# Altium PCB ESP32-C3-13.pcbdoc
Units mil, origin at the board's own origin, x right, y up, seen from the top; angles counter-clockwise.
Board outline 500 x 500 mil, 2 copper layers (Top Layer, Bottom Layer); 1 components, 0 nets, 18 pads, 0 vias.
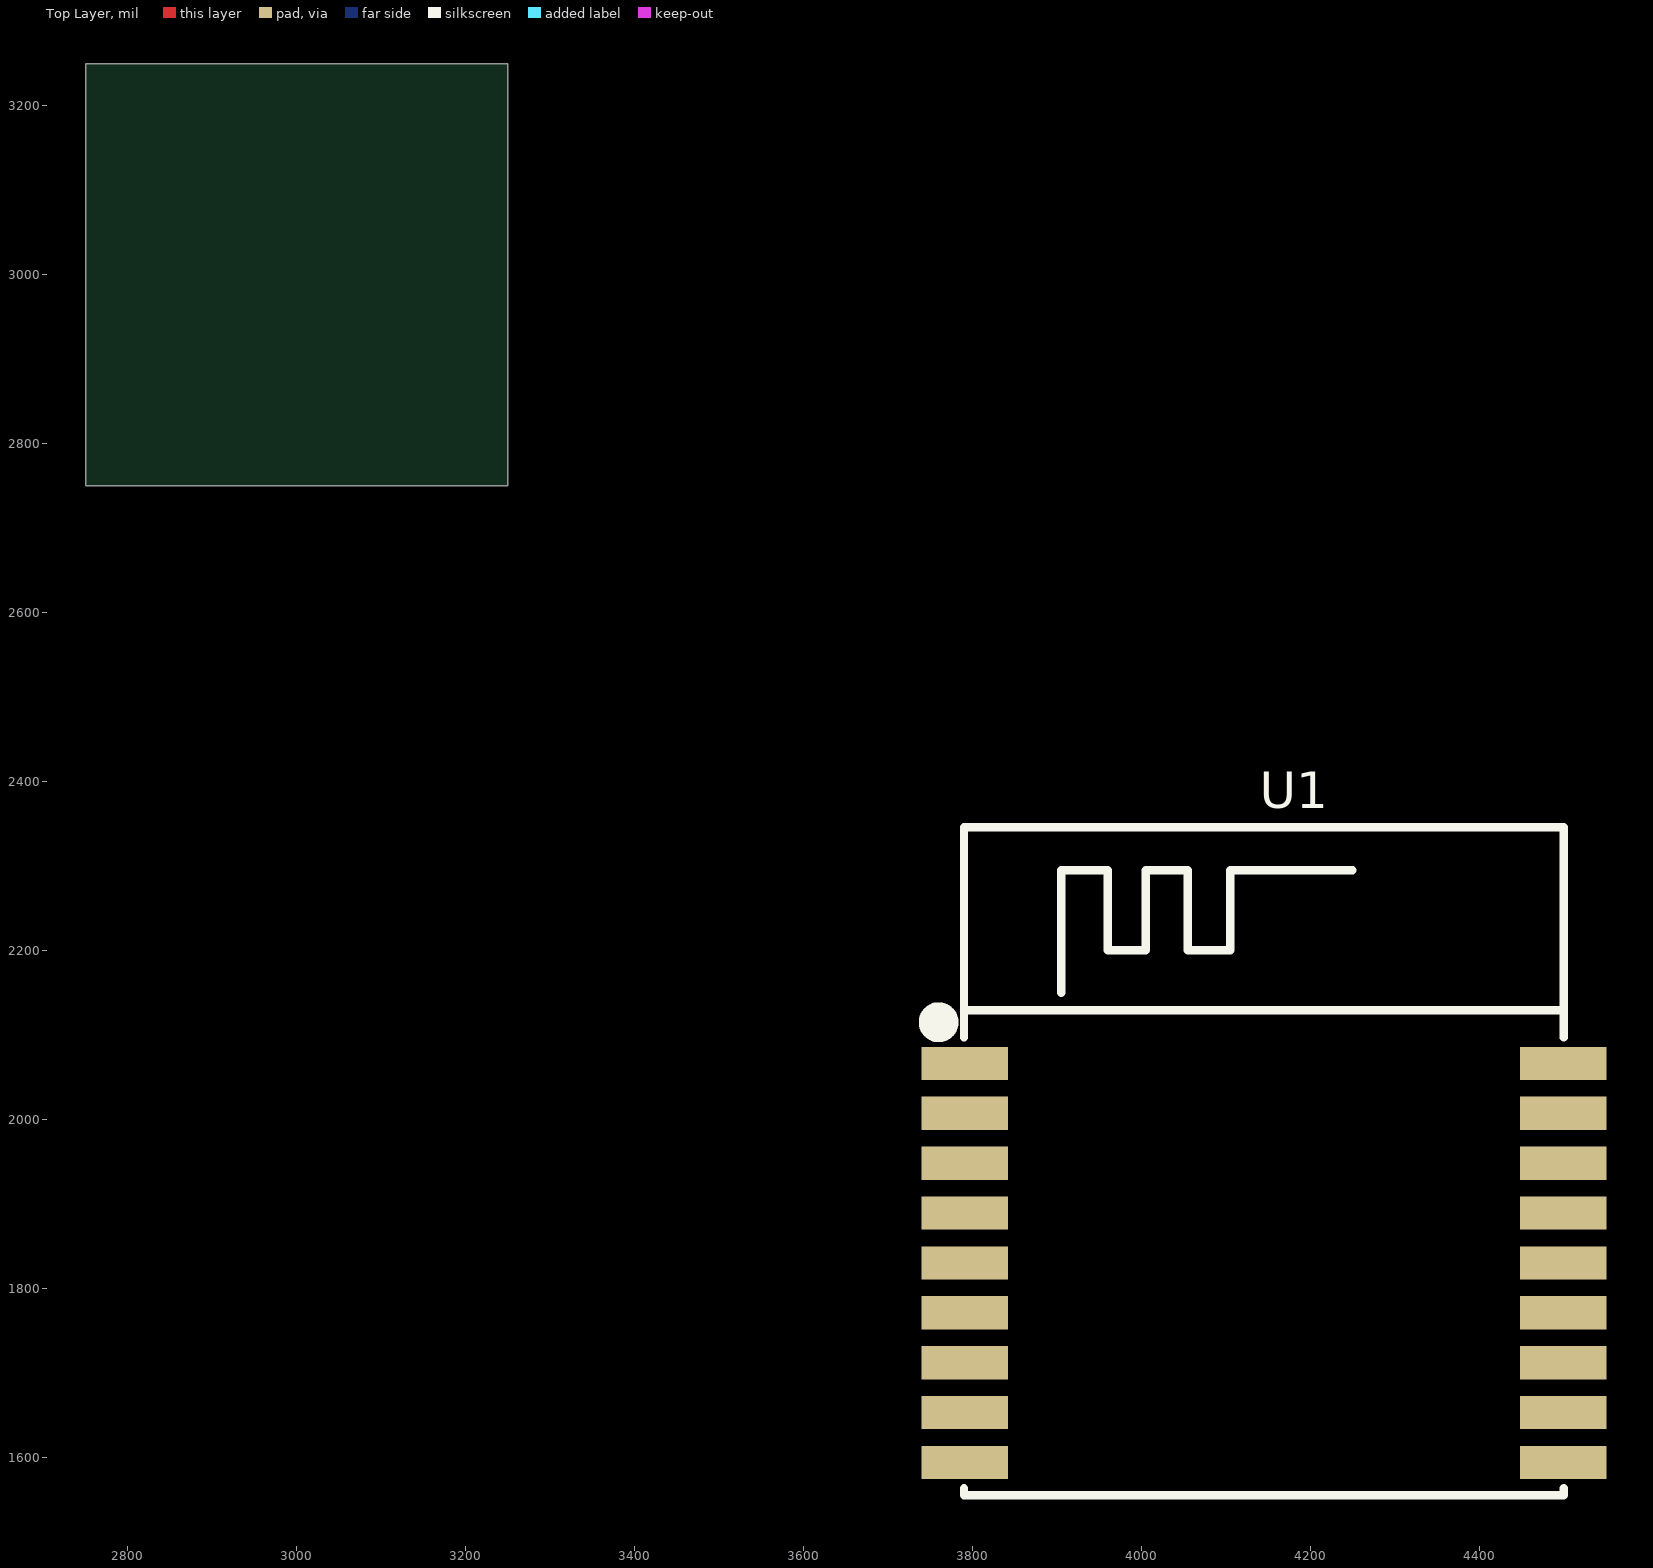
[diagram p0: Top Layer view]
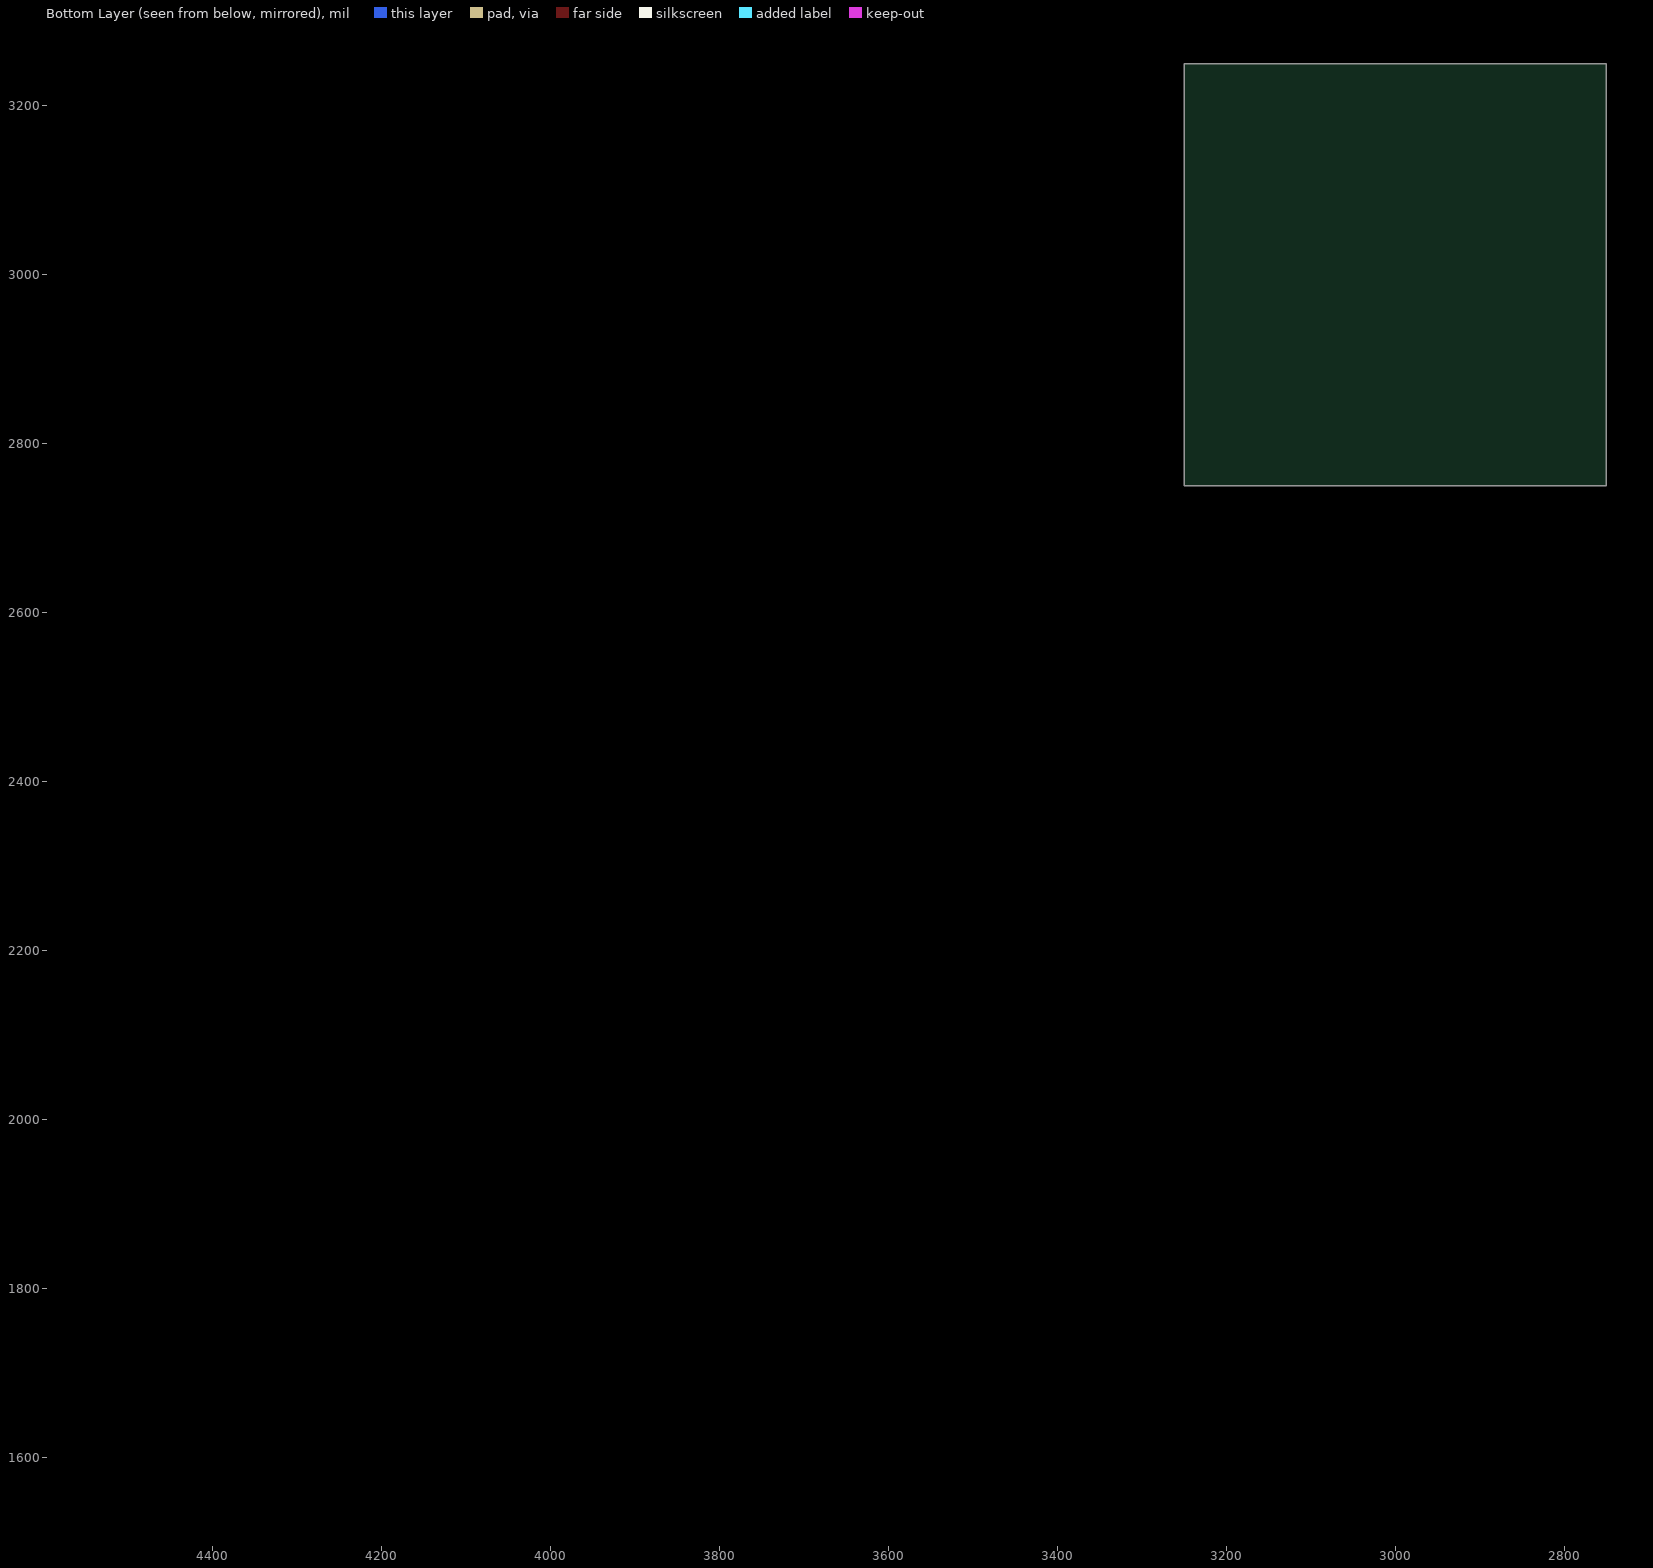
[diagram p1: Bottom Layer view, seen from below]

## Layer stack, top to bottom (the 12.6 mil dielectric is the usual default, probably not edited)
Top Solder: solder mask 0.4, Solder Resist, Dk 3.5
Top Layer: signal copper 1.4
Dielectric 1: dielectric 12.6, FR-4, Dk 4.8
Bottom Layer: signal copper 1.4
Bottom Solder: solder mask 0.4, Solder Resist, Dk 3.5

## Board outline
3250,2750 2750,2750 2750,3250 3250,3250

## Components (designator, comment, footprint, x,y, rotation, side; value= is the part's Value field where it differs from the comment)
U1 "WIRELM-SMD_ESP-C3-13-4M" WIRELM-SMD_ESP-C3-13-4M 4145,1830 r0 top

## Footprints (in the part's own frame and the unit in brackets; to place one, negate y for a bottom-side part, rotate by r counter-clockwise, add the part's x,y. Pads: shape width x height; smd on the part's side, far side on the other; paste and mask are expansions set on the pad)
WIRELM-SMD_ESP-C3-13-4M [mm]
  rect 2.6x1 smd: 1(-9,6) 2(-9,4.5) 3(-9,3) 4(-9,1.5) 5(-9,0) 6(-9,-1.5) 7(-9,-3) 8(-9,-4.5) 9(-9,-6) 10(9,-6) 11(9,-4.5) 12(9,-3) 13(9,-1.5) 14(9,0) 15(9,1.5) 16(9,3) 17(9,4.5) 18(9,6)
  silkscreen extent -10.08,-6.99 9.02,13.1

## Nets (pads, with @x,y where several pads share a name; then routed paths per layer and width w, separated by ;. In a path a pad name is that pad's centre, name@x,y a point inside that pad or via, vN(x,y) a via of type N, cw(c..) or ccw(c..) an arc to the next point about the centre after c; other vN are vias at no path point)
pads on no net: U1.1 U1.2 U1.3 U1.4 U1.5 U1.6 U1.7 U1.8 U1.9 U1.10 U1.11 U1.12 U1.13 U1.14 U1.15 U1.16 U1.17 U1.18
